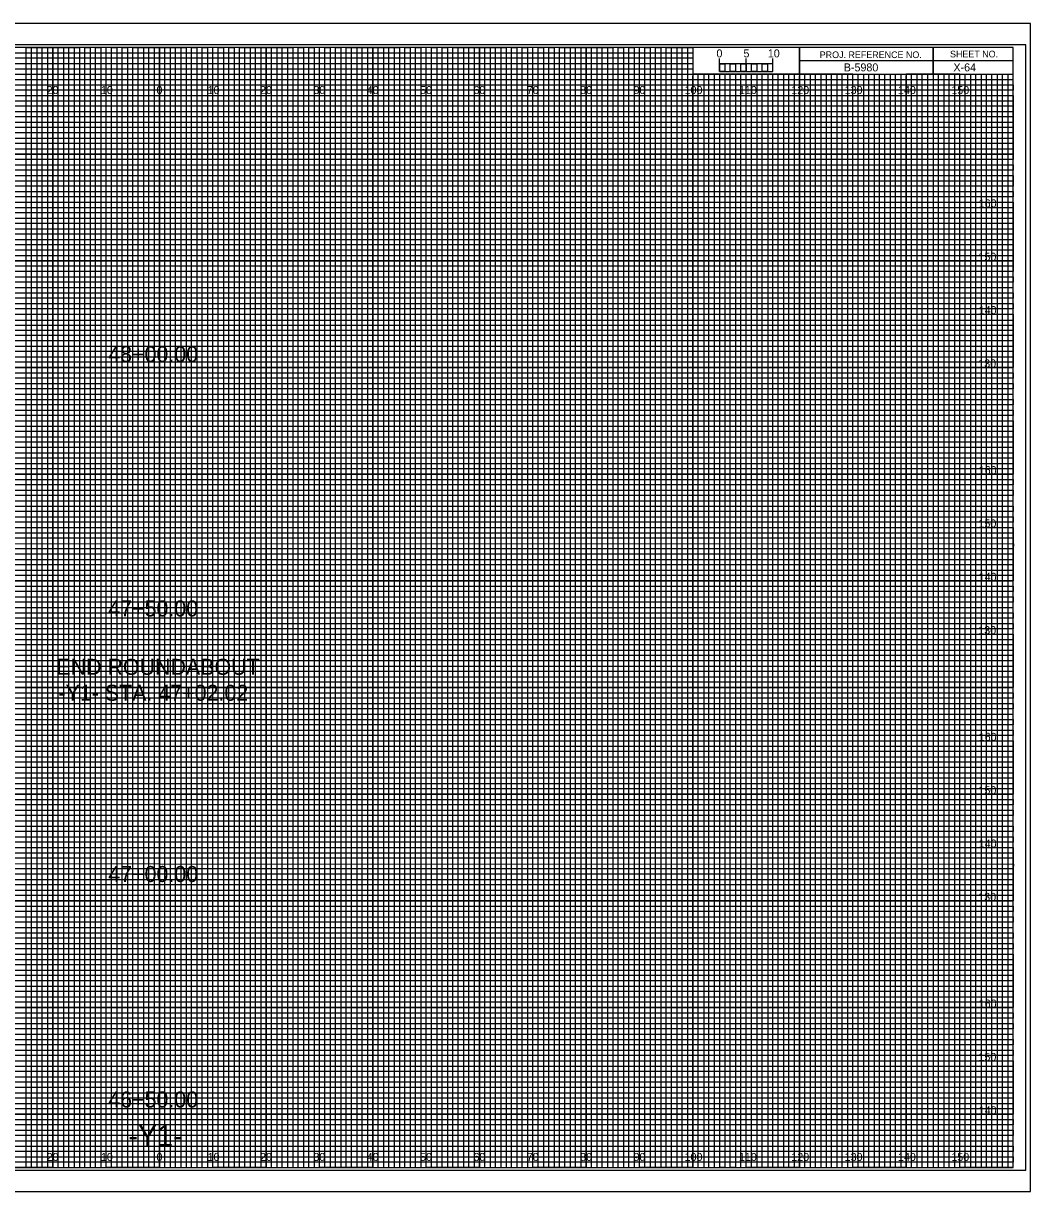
# Model space of a CAD drawing. Extents: x -13 to 323, y -5 to 4834.
# Drawn here: x 134.5 to 323.3, y 3955.5 to 4174.5 of the extents above; entities that cross this region are included whole.
import ezdxf

# ---------------------------------------------------------------- set-up
doc = ezdxf.new("R2010")
doc.units = 0
for name, color, linetype in [('Exist CMT Pavement', 7, 'Continuous'), ('Exist Cross Section Cell', 7, 'Continuous'), ('Exist XS Center Line Elevation Label', 7, 'Continuous'), ('Exist XS Ground Line', 7, 'Continuous'), ('Prop CMT Pvmt Course 1', 7, 'Continuous'), ('Prop CMT Pvmt Course 1 Wedge', 7, 'Continuous'), ('Prop CMT Pvmt Course 2', 7, 'Continuous'), ('Prop CMT Pvmt Course 2 Wedge', 7, 'Continuous'), ('Prop CMT Pvmt Course 3', 7, 'Continuous'), ('Prop CMT Pvmt Course 3 Wedge', 7, 'Continuous'), ('Prop CMT Pvmt Surface', 7, 'Continuous'), ('Prop CMT Pvmt Surface Shoulder', 7, 'Continuous'), ('Prop CMT Shld Paved Course 1', 7, 'Continuous'), ('Prop CMT Shld Paved Course 2', 7, 'Continuous'), ('Prop CMT Shld Paved Course 3', 7, 'Continuous'), ('Prop CMT Slope Grass', 7, 'Continuous'), ('Prop CMT Subgrade Earthwork', 7, 'Continuous')]:
    doc.layers.add(name, color=color, linetype=linetype)

msp = doc.modelspace()

# ---------------------------------------------------------------- linework, layer by layer
at = {"layer": 'Exist XS Center Line Elevation Label'}
for points in [[(125, 3960), (135, 3960), (135, 4170), (145, 4170), (145, 3960), (155, 3960), (155, 4170), (165, 4170), (165, 3960), (175, 3960), (175, 4170), (185, 4170), (185, 3960), (195, 3960), (195, 4170), (205, 4170), (205, 3960), (215, 3960), (215, 4170), (225, 4170), (225, 3960), (235, 3960), (235, 4170), (245, 4170), (245, 3960), (255, 3960), (255, 4170), (259.93, 4170), (260, 4170), (260, 4165), (264.99, 4165), (264.99, 3960), (275, 3960), (275, 4165), (285, 4165), (285, 3960), (295, 3960), (295, 4165), (305, 4165), (305, 3960), (315, 3960), (315, 4165)], [(0, 4165), (275, 4165)], [(0, 4145), (320, 4145), (320, 4155), (0, 4155)], [(0, 4125), (320, 4125), (320, 4135), (0, 4135)], [(0, 4105), (320, 4105), (320, 4115), (0, 4115)], [(0, 4085), (320, 4085), (320, 4095), (0, 4095)], [(0, 4065), (320, 4065), (320, 4075), (0, 4075)], [(0, 4045), (320, 4045), (320, 4055), (0, 4055)], [(0, 4025), (320, 4025), (320, 4035), (0, 4035)], [(0, 4005), (320, 4005), (320, 4015), (0, 4015)], [(0, 3985), (320, 3985), (320, 3995), (0, 3995)], [(0, 3965), (320, 3965), (320, 3975), (0, 3975)]]:
    msp.add_lwpolyline(points, dxfattribs=at)
at = {"layer": 'Exist XS Ground Line'}
for p, q in [((150, 4170), (140, 4170)), ((140, 4170), (140, 3960)), ((150, 3960), (150, 4170)), ((170, 4170), (160, 4170)), ((160, 4170), (160, 3960)), ((170, 3960), (170, 4170)), ((190, 4170), (180, 4170)), ((180, 4170), (180, 3960)), ((190, 3960), (190, 4170)), ((210, 4170), (200, 4170)), ((200, 4170), (200, 3960)), ((210, 3960), (210, 4170)), ((230, 4170), (220, 4170)), ((220, 4170), (220, 3960)), ((230, 3960), (230, 4170)), ((250, 4170), (240, 4170)), ((240, 4170), (240, 3960)), ((250, 3960), (250, 4170)), ((260, 4170), (260, 3960)), ((270, 3960), (270, 4165)), ((290, 4165), (280, 4165)), ((280, 4165), (280, 3960)), ((290, 3960), (290, 4165)), ((310, 4165), (300, 4165)), ((300, 4165), (300, 3960)), ((310, 3960), (310, 4165)), ((140, 3960), (130, 3960)), ((160, 3960), (150, 3960)), ((180, 3960), (170, 3960)), ((200, 3960), (190, 3960)), ((220, 3960), (210, 3960)), ((240, 3960), (230, 3960)), ((260, 3960), (250, 3960)), ((280, 3960), (270, 3960)), ((300, 3960), (290, 3960)), ((320, 3960), (310, 3960)), ((320, 3960), (320, 3960))]:
    msp.add_line(p, q, dxfattribs=at)
for points in [[(0, 4160), (320, 4160), (320, 4150), (0, 4150)], [(0, 4140), (320, 4140), (320, 4130), (0, 4130)], [(0, 4120), (320, 4120), (320, 4110), (0, 4110)], [(0, 4100), (320, 4100), (320, 4090), (0, 4090)], [(0, 4080), (320, 4080), (320, 4070), (0, 4070)], [(0, 4060), (320, 4060), (320, 4050), (0, 4050)], [(0, 4040), (320, 4040), (320, 4030), (0, 4030)], [(0, 4020), (320, 4020), (320, 4010), (0, 4010)], [(0, 4000), (320, 4000), (320, 3990), (0, 3990)], [(0, 3980), (320, 3980), (320, 3970), (0, 3970)]]:
    msp.add_lwpolyline(points, dxfattribs=at)
at = {"layer": 'Prop CMT Pvmt Course 1'}
for p, q in [((267, 4165), (266.01, 4165)), ((266.01, 4165), (266.01, 3960)), ((267, 3960), (267, 4165)), ((269, 4165), (268, 4165)), ((268, 4165), (268, 3960)), ((269, 3960), (269, 4165)), ((266.01, 3960), (265, 3960)), ((268, 3960), (267, 3960))]:
    msp.add_line(p, q, dxfattribs=at)
for points in [[(135, 3960), (136, 3960), (136, 4170), (137, 4170), (137, 3960)], [(137, 3960), (138, 3960), (138, 4170), (139, 4170), (139, 3960)], [(140, 3960), (141, 3960), (141, 4170), (142, 4170), (142, 3960)], [(142, 3960), (143, 3960), (143, 4170), (144, 4170), (144, 3960)], [(145, 3960), (146, 3960), (146, 4170), (147, 4170), (147, 3960)], [(147, 3960), (148, 3960), (148, 4170), (149, 4170), (149, 3960)], [(150, 3960), (151, 3960), (151, 4170), (152, 4170), (152, 3960)], [(152, 3960), (153, 3960), (153, 4170), (154, 4170), (154, 3960)], [(155, 3960), (156, 3960), (156, 4170), (157, 4170), (157, 3960)], [(157, 3960), (158, 3960), (158, 4170), (159, 4170), (159, 3960)], [(160, 3960), (161, 3960), (161, 4170), (162, 4170), (162, 3960)], [(162, 3960), (163, 3960), (163, 4170), (164, 4170), (164, 3960)], [(165, 3960), (166, 3960), (166, 4170), (167, 4170), (167, 3960)], [(167, 3960), (168, 3960), (168, 4170), (169, 4170), (169, 3960)], [(170, 3960), (171, 3960), (171, 4170), (172, 4170), (172, 3960)], [(172, 3960), (173, 3960), (173, 4170), (174, 4170), (174, 3960)], [(175, 3960), (176, 3960), (176, 4170), (177, 4170), (177, 3960)], [(177, 3960), (178, 3960), (178, 4170), (179, 4170), (179, 3960)], [(180, 3960), (181, 3960), (181, 4170), (182, 4170), (182, 3960)], [(182, 3960), (183, 3960), (183, 4170), (184, 4170), (184, 3960)], [(185, 3960), (186, 3960), (186, 4170), (187, 4170), (187, 3960)], [(187, 3960), (188, 3960), (188, 4170), (189, 4170), (189, 3960)], [(190, 3960), (191, 3960), (191, 4170), (192, 4170), (192, 3960)], [(192, 3960), (193, 3960), (193, 4170), (194, 4170), (194, 3960)], [(195, 3960), (196, 3960), (196, 4170), (197, 4170), (197, 3960)], [(197, 3960), (198, 3960), (198, 4170), (199, 4170), (199, 3960)], [(200, 3960), (201, 3960), (201, 4170), (202, 4170), (202, 3960)], [(202, 3960), (203, 3960), (203, 4170), (204, 4170), (204, 3960)], [(205, 3960), (206, 3960), (206, 4170), (207, 4170), (207, 3960)], [(207, 3960), (208, 3960), (208, 4170), (209, 4170), (209, 3960)], [(210, 3960), (211, 3960), (211, 4170), (212, 4170), (212, 3960)], [(212, 3960), (213, 3960), (213, 4170), (214, 4170), (214, 3960)], [(215, 3960), (216, 3960), (216, 4170), (217, 4170), (217, 3960)], [(217, 3960), (218, 3960), (218, 4170), (219, 4170), (219, 3960)], [(220, 3960), (221, 3960), (221, 4170), (222, 4170), (222, 3960)], [(222, 3960), (223, 3960), (223, 4170), (224, 4170), (224, 3960)], [(225, 3960), (226, 3960), (226, 4170), (227, 4170), (227, 3960)], [(227, 3960), (228, 3960), (228, 4170), (229, 4170), (229, 3960)], [(230, 3960), (231, 3960), (231, 4170), (232, 4170), (232, 3960)], [(232, 3960), (233, 3960), (233, 4170), (234, 4170), (234, 3960)], [(235, 3960), (236, 3960), (236, 4170), (237, 4170), (237, 3960)], [(237, 3960), (238, 3960), (238, 4170), (239, 4170), (239, 3960)], [(240, 3960), (241, 3960), (241, 4170), (242, 4170), (242, 3960)], [(242, 3960), (243, 3960), (243, 4170), (244, 4170), (244, 3960)], [(245, 3960), (246, 3960), (246, 4170), (247, 4170), (247, 3960)], [(247, 3960), (248, 3960), (248, 4170), (249, 4170), (249, 3960)], [(250, 3960), (251, 3960), (251, 4170), (252, 4170), (252, 3960)], [(252, 3960), (253, 3960), (253, 4170), (254, 4170), (254, 3960)], [(255, 3960), (256, 3960), (256, 4170), (257, 4170), (257, 3960)], [(257, 3960), (258, 3960), (258, 4170), (259, 4170), (259, 3960)], [(260, 3960), (261, 3960), (261, 4165), (262.02, 4165), (262.02, 3960)], [(262, 3960), (263, 3960), (263, 4165), (263.99, 4165), (263.99, 3960)], [(270, 3960), (270.98, 3960), (270.98, 4165), (272, 4165), (272, 3960)], [(272, 3960), (273, 3960), (273, 4165), (274.05, 4165), (274.05, 3960)], [(275, 3960), (276, 3960), (276, 4165), (277, 4165), (277, 3960)], [(277, 3960), (278, 3960), (278, 4165), (279, 4165), (279, 3960)], [(280, 3960), (281, 3960), (281, 4165), (282, 4165), (282, 3960)], [(282, 3960), (283, 3960), (283, 4165), (284, 4165), (284, 3960)], [(285, 3960), (286, 3960), (286, 4165), (287, 4165), (287, 3960)], [(287, 3960), (288, 3960), (288, 4165), (289, 4165), (289, 3960)], [(290, 3960), (291, 3960), (291, 4165), (292, 4165), (292, 3960)], [(292, 3960), (293, 3960), (293, 4165), (294, 4165), (294, 3960)], [(295, 3960), (296, 3960), (296, 4165), (297, 4165), (297, 3960)], [(297, 3960), (298, 3960), (298, 4165), (299, 4165), (299, 3960)], [(300, 3960), (301, 3960), (301, 4165), (302, 4165), (302, 3960)], [(302, 3960), (303, 3960), (303, 4165), (304, 4165), (304, 3960)], [(305, 3960), (306, 3960), (306, 4165), (307, 4165), (307, 3960)], [(307, 3960), (308, 3960), (308, 4165), (309, 4165), (309, 3960)], [(310, 3960), (311, 3960), (311, 4165), (312, 4165), (312, 3960)], [(312, 3960), (313, 3960), (313, 4165), (314, 4165), (314, 3960)], [(315, 3960), (316, 3960), (316, 4165), (317, 4165), (317, 3960)], [(317, 3960), (318, 3960), (318, 4165), (319, 4165), (319, 3960)]]:
    msp.add_lwpolyline(points, dxfattribs=at)
at = {"layer": 'Prop CMT Pvmt Course 2'}
for p, q in [((323.3, 4174.5), (-13.4, 4174.5)), ((-13.4, 3955.5), (323.3, 3955.5))]:
    msp.add_line(p, q, dxfattribs=at)
at = {"layer": 'Prop CMT Pvmt Surface Shoulder'}
for p, q in [((305, 4170), (305, 4165)), ((305, 4165), (305, 4170)), ((280, 4167.5), (280, 4165)), ((320, 4167.49), (280, 4167.49)), ((280, 4165), (320, 4165))]:
    msp.add_line(p, q, dxfattribs=at)
for points in [[(320, 4170), (0, 4170), (0, 3960), (320, 3960)], [(280, 4170), (260, 4170), (260, 4165.03), (280, 4165.03)], [(320, 4170), (280, 4170), (280, 4165), (320, 4165)]]:
    msp.add_lwpolyline(points, close=True, dxfattribs=at)
at = {"layer": 'Prop CMT Shld Paved Course 1'}
msp.add_lwpolyline([(-13.4, 3955.5), (323.3, 3955.5), (323.3, 4174.5), (-13.4, 4174.5)], close=True, dxfattribs=at)
at = {"layer": 'Prop CMT Shld Paved Course 2'}
msp.add_lwpolyline([(-10.8, 3959.5), (322.4, 3959.5), (322.4, 4170.5), (-10.8, 4170.5)], close=True, dxfattribs=at)
at = {"layer": 'Prop CMT Shld Paved Course 3'}
for p, q in [((140, 3960), (140, 4170)), ((150, 3960), (150, 4170)), ((160, 3960), (160, 4170)), ((170, 3960), (170, 4170)), ((180, 3960), (180, 4170)), ((190, 3960), (190, 4170)), ((200, 3960), (200, 4170)), ((210, 3960), (210, 4170)), ((220, 3960), (220, 4170)), ((230, 3960), (230, 4170)), ((240, 3960), (240, 4170)), ((250, 3960), (250, 4170)), ((260, 3960), (260, 4164.69)), ((270, 3960), (270, 4164.69)), ((280, 3960), (280, 4164.69)), ((290, 3960), (290, 4164.69)), ((300, 3960), (300, 4164.69)), ((310, 3960), (310, 4164.69)), ((0, 4160), (320, 4160)), ((0, 4150), (320, 4150)), ((0, 4140), (320, 4140)), ((0, 4130), (320, 4130)), ((0, 4120), (320, 4120)), ((0, 4110), (320, 4110)), ((0, 4100), (320, 4100)), ((0, 4090), (320, 4090)), ((0, 4080), (320, 4080)), ((0, 4070), (320, 4070)), ((0, 4060), (320, 4060)), ((0, 4050), (320, 4050)), ((0, 4040), (320, 4040)), ((0, 4030), (320, 4030)), ((0, 4020), (320, 4020)), ((0, 4010), (320, 4010)), ((0, 4000), (320, 4000)), ((0, 3990), (320, 3990)), ((0, 3980), (320, 3980)), ((0, 3970), (320, 3970))]:
    msp.add_line(p, q, dxfattribs=at)
at = {"layer": 'Prop CMT Slope Grass'}
for p, q in [((0, 4169), (260, 4169)), ((260, 4167.98), (0, 4167.98)), ((260, 4169), (260, 4167.98)), ((0, 4167), (260, 4167)), ((260, 4165.89), (0, 4165.89)), ((260, 4167), (260, 4165.89)), ((0, 4164), (320, 4164))]:
    msp.add_line(p, q, dxfattribs=at)
for points in [[(0, 4163), (270, 4163), (320, 4163), (320, 4162), (0, 4162)], [(0, 4161), (320, 4161), (320, 4159), (0, 4159)], [(0, 4158), (320, 4158), (320, 4157), (0, 4156.98)], [(0, 4156), (320, 4156), (320, 4154), (0, 4154)], [(0, 4153), (320, 4153), (320, 4152), (0, 4152)], [(0, 4151), (320, 4151), (320, 4149), (0, 4149)], [(0, 4148), (320, 4148), (320, 4147), (0, 4147)], [(0, 4146), (320, 4146), (320, 4144), (0, 4144)], [(0, 4143), (320, 4143), (320, 4142), (0, 4142)], [(0, 4141), (320, 4141), (320, 4139), (0, 4139)], [(0, 4138), (320, 4138), (320, 4137), (0, 4137)], [(0, 4136), (320, 4136), (320, 4133.95), (320, 4133), (320, 4132), (0, 4132)], [(0, 4134), (320, 4134), (320, 4133), (0, 4133)], [(0, 4131), (320, 4131), (320, 4129), (0, 4129.03)], [(0, 4129.03), (320, 4129), (320, 4128), (0, 4128)], [(0, 4127), (320, 4127), (320, 4126), (0, 4126)], [(0, 4124), (320, 4124), (320, 4123), (0, 4123)], [(0, 4122), (320, 4122), (320, 4121), (0, 4121)], [(-0.07, 4118.89), (320, 4118.89), (320, 4117.88), (-0.07, 4117.88)], [(0, 4117), (320, 4117), (320, 4116), (0, 4116)], [(0, 4114), (320, 4114), (320, 4113), (0, 4113)], [(0, 4112), (320, 4112), (320, 4111), (0, 4111)], [(0, 4109), (320, 4109), (320, 4108), (0, 4108)], [(0, 4107), (320, 4107), (320, 4106), (0, 4106)], [(0, 4104), (320, 4104), (320, 4103), (0, 4103)], [(0, 4102), (320, 4102), (320, 4101), (0, 4101)], [(0, 4099), (320, 4099), (319.99, 4097.98), (0, 4098)], [(0, 4097), (320, 4097), (320, 4096), (0, 4096)], [(0, 4094), (320, 4094), (320, 4093), (0, 4093)], [(0, 4092), (320, 4092), (320, 4091), (0, 4091)], [(0, 4089), (320, 4089), (320, 4088), (0, 4088)], [(0, 4087), (320, 4087), (320, 4086), (0, 4086)], [(0, 4084), (320, 4084), (320, 4083), (0, 4083)], [(0, 4082), (320, 4082), (320, 4081), (0, 4081)], [(0, 4079), (320, 4079), (320, 4078), (0, 4078)], [(0, 4076.99), (320.07, 4076.91), (320, 4076), (0, 4076)], [(0, 4074), (320, 4074), (320, 4073), (0, 4073)], [(0, 4072), (320, 4072), (320, 4071), (0, 4071)], [(0, 4069), (320, 4069), (320, 4068), (0, 4068)], [(0, 4067), (320, 4067), (320, 4066), (0, 4066)], [(0, 4064), (320, 4064), (320, 4063), (0, 4063)], [(0, 4062), (320, 4062), (320, 4061), (0, 4061)], [(0, 4059), (320, 4059), (320, 4058), (0, 4058)], [(0, 4057), (320, 4057), (320, 4056), (0, 4056)], [(0, 4054), (320, 4054), (320, 4053), (0, 4053)], [(0, 4052), (320, 4052), (320, 4051), (0, 4051)], [(0, 4049), (320, 4049), (320, 4048), (0, 4048)], [(0, 4047), (320, 4047), (320, 4046), (0, 4046)], [(0, 4044), (320, 4044), (320, 4043), (0, 4043)], [(0, 4042), (320, 4042), (320, 4041), (0, 4041)], [(0, 4039), (320, 4039), (319.99, 4037.98), (0, 4038)], [(0, 4037), (320, 4037), (320, 4036), (0, 4036)], [(0, 4034), (320, 4034), (320, 4033), (0, 4033)], [(0, 4032), (320, 4032), (320, 4031), (0, 4031)], [(0, 4029), (320, 4029), (320, 4028), (0, 4028)], [(0, 4027), (320, 4027), (320, 4026), (0, 4026)], [(0, 4024), (320, 4024), (320, 4023), (0, 4023)], [(0, 4022), (320, 4022), (320, 4021), (0, 4021)], [(0, 4019), (320, 4019), (320, 4018), (0, 4018)], [(0, 4016.99), (320.07, 4016.91), (320, 4016), (0, 4016)], [(0, 4014), (320, 4014), (320, 4013), (0, 4013)], [(0, 4012), (320, 4012), (320, 4011), (0, 4011)], [(0, 4009), (320, 4009), (320, 4008), (0, 4008)], [(0, 4007), (320, 4007), (320, 4006), (0, 4006)], [(0, 4004), (320, 4004), (320, 4003), (0, 4003)], [(0, 4002), (320, 4002), (320, 4001), (0, 4001)], [(0, 3999), (320, 3999), (320, 3998), (0, 3998)], [(0, 3997), (320, 3997), (320, 3996), (0, 3996)], [(0, 3994), (320, 3994), (320, 3993), (0, 3993)], [(0, 3992), (320, 3992), (320, 3991), (0, 3991)], [(0, 3989), (320, 3989), (320, 3988), (0, 3988)], [(0, 3987), (320, 3987), (320, 3986), (0, 3986)], [(0, 3984), (320, 3984), (320, 3983), (0, 3983)], [(0, 3982), (320, 3982), (320, 3981), (0, 3981)], [(0, 3979), (320, 3979), (320, 3978), (0, 3978)], [(0, 3977), (320, 3977), (320, 3976), (0, 3976)], [(0, 3974), (320, 3974), (320, 3973), (0, 3973)], [(0, 3972), (320, 3972), (320, 3971), (0, 3971)], [(0, 3969), (320, 3969), (320, 3968), (0, 3968)], [(0, 3967), (320, 3967), (320, 3966), (0, 3966)], [(0, 3964), (320, 3964), (320, 3963), (0, 3963)], [(0, 3962), (320, 3962), (320, 3961), (0, 3961)]]:
    msp.add_lwpolyline(points, dxfattribs=at)
at = {"layer": 'Prop CMT Subgrade Earthwork'}
for p, q in [((265, 4165.49), (265, 4167.9)), ((265, 4166.9), (265, 4167.9)), ((270, 4165.49), (270, 4167.9)), ((275, 4165.49), (275, 4167.9)), ((275, 4166.9), (275, 4167.9))]:
    msp.add_line(p, q, dxfattribs=at)
for points in [[(275, 4166.9), (265, 4166.9), (265, 4165.49), (275, 4165.49)], [(265, 4166.9), (266, 4166.9), (266, 4165.49), (265, 4165.49)], [(267, 4166.9), (268, 4166.9), (268, 4165.49), (267, 4165.49)], [(269, 4166.9), (270, 4166.9), (270, 4165.49), (269, 4165.49)], [(271, 4166.9), (272, 4166.9), (272, 4165.49), (271, 4165.49)], [(273, 4166.9), (274, 4166.9), (274, 4165.49), (273, 4165.49)]]:
    msp.add_lwpolyline(points, close=True, dxfattribs=at)

# ---------------------------------------------------------------- texts
at = {"layer": 'Exist CMT Pavement'}
msp.add_text('-Y1-', height=4, dxfattribs=at).set_placement((154.21, 3964))
at = {"layer": 'Exist Cross Section Cell'}
for s, p in [('20', (138.86, 4161.25)), ('10', (149.04, 4161.25)), ('0', (159.45, 4161.25)), ('0', (159.45, 4161.25)), ('10', (169.04, 4161.25)), ('20', (178.86, 4161.25)), ('30', (188.86, 4161.25)), ('40', (198.86, 4161.25)), ('50', (208.86, 4161.25)), ('60', (218.86, 4161.25)), ('70', (228.86, 4161.25)), ('80', (238.86, 4161.25)), ('90', (248.86, 4161.25)), ('100', (258.44, 4161.25)), ('110', (268.62, 4161.25)), ('120', (278.44, 4161.25)), ('130', (288.44, 4161.25)), ('140', (298.44, 4161.25)), ('150', (308.44, 4161.25)), ('20', (138.86, 3961.25)), ('10', (149.04, 3961.25)), ('0', (159.45, 3961.25)), ('0', (159.45, 3961.25)), ('10', (169.04, 3961.25)), ('20', (178.86, 3961.25)), ('30', (188.86, 3961.25)), ('40', (198.86, 3961.25)), ('50', (208.86, 3961.25)), ('60', (218.86, 3961.25)), ('70', (228.86, 3961.25)), ('80', (238.86, 3961.25)), ('90', (248.86, 3961.25)), ('100', (258.44, 3961.25)), ('110', (268.62, 3961.25)), ('120', (278.44, 3961.25)), ('130', (288.44, 3961.25)), ('140', (298.44, 3961.25)), ('150', (308.44, 3961.25))]:
    msp.add_text(s, height=1.5, dxfattribs=at).set_placement(p)
at = {"layer": 'Prop CMT Pvmt Course 1 Wedge'}
for s, p in [('48+00.00', (150.41, 4111)), ('47+50.00', (150.41, 4063.33)), ('END ROUNDABOUT', (140.68, 4052.38)), ('-Y1- STA. 47+02.02', (141.08, 4047.51)), ('47+00.00', (150.41, 4013.54)), ('46+50.00', (150.41, 3971.28))]:
    msp.add_text(s, height=3, dxfattribs=at).set_placement(p)
at = {"layer": 'Prop CMT Pvmt Course 2 Wedge'}
msp.add_text('X-64', height=1.5, dxfattribs=at).set_placement((308.83, 4165.5))
at = {"layer": 'Prop CMT Pvmt Course 3'}
for s, p in [('160', (313.57, 4140)), ('150', (313.52, 4130)), ('140', (313.57, 4120)), ('130', (313.49, 4110)), ('160', (313.57, 4090)), ('150', (313.52, 4080)), ('140', (313.57, 4070)), ('130', (313.49, 4060)), ('160', (313.57, 4040)), ('150', (313.52, 4030)), ('140', (313.57, 4020)), ('130', (313.49, 4010)), ('160', (313.57, 3990)), ('150', (313.52, 3980)), ('140', (313.57, 3970))]:
    msp.add_text(s, height=1.5, dxfattribs=at).set_placement(p)
at = {"layer": 'Prop CMT Pvmt Course 3 Wedge'}
msp.add_text('B-5980', height=1.5, dxfattribs=at).set_placement((288.28, 4165.5))
at = {"layer": 'Prop CMT Pvmt Surface'}
for s, p in [('5', (269.47, 4168.12)), ('10', (274.04, 4168.12))]:
    msp.add_text(s, height=1.5, dxfattribs=at).set_placement(p)
at = {"layer": 'Prop CMT Pvmt Surface Shoulder'}
for s, p in [('PROJ. REFERENCE NO.', (283.77, 4167.99)), ('SHEET NO.', (308.19, 4168.12))]:
    msp.add_text(s, height=1.25, dxfattribs=at).set_placement(p)
at = {"layer": 'Prop CMT Subgrade Earthwork'}
msp.add_text('0', height=1.5, dxfattribs=at).set_placement((264.41, 4168.12))

doc.saveas('drawing.dxf')
